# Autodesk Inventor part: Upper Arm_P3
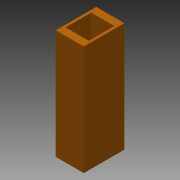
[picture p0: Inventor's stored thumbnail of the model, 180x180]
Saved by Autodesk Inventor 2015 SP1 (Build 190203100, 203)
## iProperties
Created: 2008-11
Part Number: Upper Arm_P3
Document SubType Name: Modeling
Designer: dwoollam
Density: 7.85 g/cm^3
Material: Steel
Appearance: Orange
Mass: 103909 g
Surface Area: 9820.7 cm^2
Volume: 13236.8 cm^3
Dwg_Category: Clearance_Mewp
INSTALLATION: False
CIVIL_WORK: False
EARTHING: False
MOUNTING: False
Author: dwoollam
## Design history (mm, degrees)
sketch "Sketch1"
  geometry: L1 (-70, 77.5)-(70, 77.5); L2 (70, 77.5)-(70, -77.5); L3 (70, -77.5)-(-70, -77.5); L4 (-70, -77.5)-(-70, 77.5); L5 (-85, 122.5)-(85, 122.5); L6 (85, 122.5)-(85, -122.5); L7 (85, -122.5)-(-85, -122.5); L8 (-85, -122.5)-(-85, 122.5); 5 further points
  constraints: 16 end point, 4 midpoint, 4 parallel, 2 horizontal, 2 horizontal alignment, 2 perpendicular, 2 vertical alignment
  dimensions: "d35" = 140 distance of L1.start L1.end; "d36" = 170 distance of L5.start L5.end; "d37" = 245 distance of L5.end L6.end; "d38" = 45 distance between parallel lines of L5 L1
extrude "End Stop" new body sketch "Sketch1" stored distance "d21" = 663.5; taper "d22" = 0 deg
body "Solid1"
